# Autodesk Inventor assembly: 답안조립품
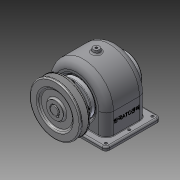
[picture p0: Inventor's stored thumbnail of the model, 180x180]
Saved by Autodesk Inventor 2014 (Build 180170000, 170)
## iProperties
Created: 2015-09
Part Number: 답안조립품
Document SubType Name: Assembly
Designer: Administrator
Author: Administrator
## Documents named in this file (14)
- C:\Users\Administrator\Desktop\450907V1043\답안조립품.iam
- C:\Users\Administrator\Desktop\450907V1043\1-본체.ipt
- C:\Users\Administrator\Desktop\450907V1043\V-벨트풀리.ipt
- C:\Users\Administrator\Desktop\450907V1043\뒤커버.ipt
- C:\Users\Administrator\Desktop\450907V1043\멈춤나사 - M4x10.ipt
- C:\Users\Administrator\Desktop\450907V1043\베어링 6203.ipt
- C:\Users\Administrator\Desktop\450907V1043\볼트 M3 x 8.ipt
- C:\Users\Administrator\Desktop\450907V1043\볼트 M3 x 10.ipt
- C:\Users\Administrator\Desktop\450907V1043\스퍼기어.ipt
- C:\Users\Administrator\Desktop\450907V1043\앞커버.ipt
- C:\Users\Administrator\Desktop\450907V1043\오일 실 17 32 8.ipt
- C:\Users\Administrator\Desktop\450907V1043\축.ipt
- C:\Users\Administrator\Desktop\450907V1043\키 - 5 x 5 x 18.ipt
- C:\Users\Administrator\Desktop\450907V1043\키 - 6 x 6 x 22.ipt
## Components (10 placed, 4 different names)
1. 1-본체:1 — 각도:1, 각도:2
2. V-벨트풀리:1
3. ISO 4762 M3 x 8:1 — 각도:1
4. ISO 4762 M3 x 8:2
5. ISO 4762 M3 x 8:3
6. ISO 4762 M3 x 8:4
7. ISO 4762 M3 x 10:1 — 각도:2
8. ISO 4762 M3 x 10:2
9. ISO 4762 M3 x 10:3
10. ISO 4762 M3 x 10:4
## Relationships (2: Angle 2)
- 각도:1 [Angle]: 1-본체:1 ↔ ISO 4762 M3 x 8:1
- 각도:2 [Angle]: 1-본체:1 ↔ ISO 4762 M3 x 10:1
